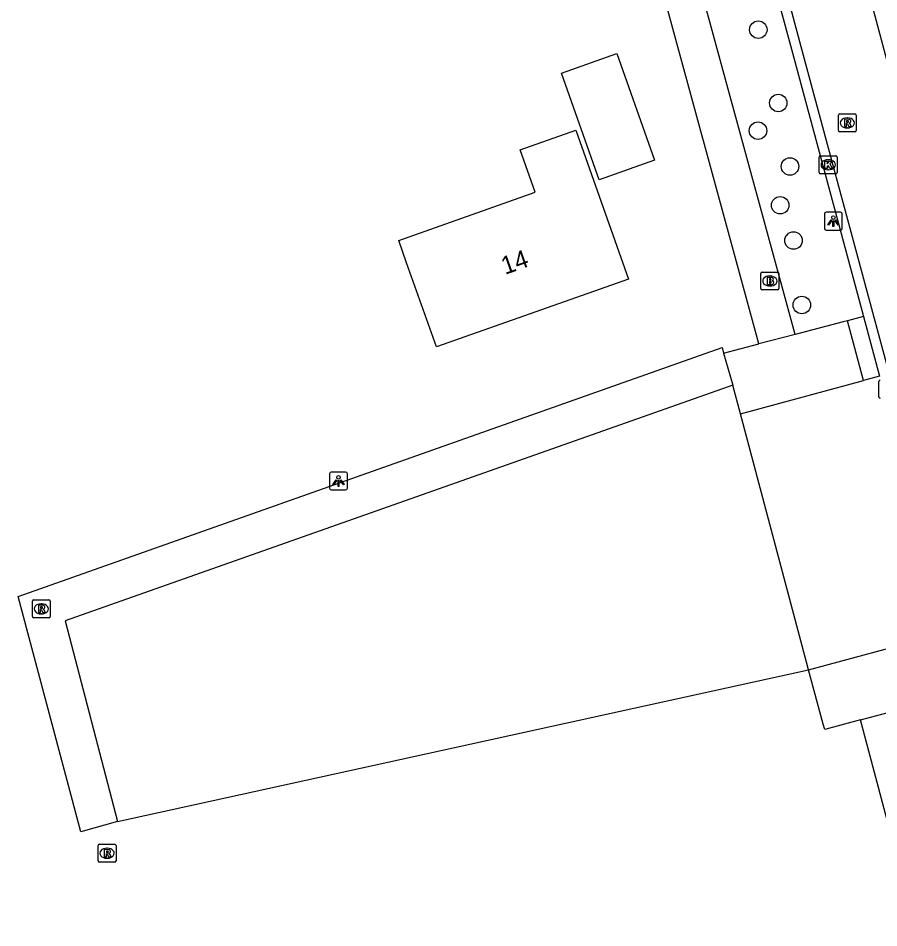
# Model space of a CAD drawing. Extents: x 162675 to 163482, y 379761 to 381227.
# Drawn here: x 162810 to 162858.2, y 380571.5 to 380622.3 of the extents above; entities that cross this region are included whole.
import ezdxf

# ---------------------------------------------------------------- set-up
doc = ezdxf.new("R2010")
doc.units = 0
for name, color, linetype in [('IMGEO_Boom', 7, 'Continuous'), ('IMGEO_Brandkraan', 7, 'Continuous'), ('IMGEO_Groenvoorziening', 7, 'Continuous'), ('IMGEO_Kolk', 7, 'Continuous'), ('IMGEO_Lichtpunt', 7, 'Continuous'), ('IMGEO_Pand', 7, 'Continuous'), ('IMGEO_Pand_nummerreeks', 7, 'Continuous'), ('IMGEO_Parkeervlak_open', 7, 'Continuous'), ('IMGEO_Rijbaan_lokaal_gesloten', 7, 'Continuous'), ('IMGEO_Rijbaan_lokaal_open', 7, 'Continuous'), ('IMGEO_Rioolput', 7, 'Continuous'), ('IMGEO_Voetpad_open', 7, 'Continuous')]:
    doc.layers.add(name, color=color, linetype=linetype)

msp = doc.modelspace()

# ---------------------------------------------------------------- linework, layer by layer
at = {"layer": 'IMGEO_Boom'}
for centre in [(162851.454, 380621.695), (162852.572, 380617.595), (162851.441, 380616.043), (162853.23, 380614.043), (162852.682, 380611.873), (162853.428, 380609.9), (162853.892, 380606.295)]:
    msp.add_circle(centre, 0.489, dxfattribs=at)
at = {"layer": 'IMGEO_Brandkraan'}
for p, q in [((162851.601, 380607.21), (162851.601, 380608.062)), ((162851.676, 380608.136), (162852.528, 380608.136)), ((162852.089, 380607.916), (162852.114, 380607.916)), ((162852.602, 380608.062), (162852.602, 380607.21)), ((162852.528, 380607.136), (162851.676, 380607.136)), ((162852.112, 380607.356), (162852.087, 380607.356))]:
    msp.add_line(p, q, dxfattribs=at)
for points in [[(162851.601, 380607.21), (162851.601, 380608.062)], [(162851.676, 380608.136), (162852.528, 380608.136)], [(162852.602, 380608.062), (162852.602, 380607.21)], [(162851.949, 380607.836), (162851.949, 380607.436), (162852.162, 380607.436)], [(162852.18, 380607.836), (162851.949, 380607.836)], [(162852.128, 380607.755), (162852.074, 380607.755), (162852.074, 380607.679)], [(162852.074, 380607.679), (162852.127, 380607.679)], [(162852.136, 380607.603), (162852.074, 380607.603), (162852.074, 380607.522)], [(162852.074, 380607.522), (162852.136, 380607.522)], [(162852.528, 380607.136), (162851.676, 380607.136)]]:
    msp.add_lwpolyline(points, dxfattribs=at)
for centre, radius, start, end in [((162851.678, 380608.06), 0.0765, 91.552, 178.448), ((162851.678, 380608.06), 0.0765, 91.552, 178.448), ((162852.526, 380608.06), 0.0765, 1.552, 88.448), ((162852.526, 380608.06), 0.0765, 1.552, 88.448), ((162852.129, 380607.717), 0.0379, 267.8285, 90.9355), ((162852.137, 380607.562), 0.0404, 269.8759, 90.5077), ((162852.168, 380607.687), 0.251, 268.6676, 293.5347), ((162852.184, 380607.691), 0.145, 59.4692, 91.5367), ((162852.209, 380607.738), 0.0922, 285.5137, 58.1501), ((162852.214, 380607.546), 0.105, 301.3115, 78.989), ((162851.678, 380607.212), 0.0765, 181.552, 268.448), ((162851.678, 380607.212), 0.0765, 181.552, 268.448), ((162852.526, 380607.212), 0.0765, 271.552, 358.448), ((162852.526, 380607.212), 0.0765, 271.552, 358.448)]:
    msp.add_arc(centre, radius, start, end, dxfattribs=at)
for centre, major_axis, ratio, start_param, end_param in [((162852.088, 380607.636), (-0.387, 0.002), 0.722429, 4.712389, 7.853982), ((162852.113, 380607.636), (-0.39, 0.002), 0.717154, 1.570796, 4.712389)]:
    msp.add_ellipse(centre, major_axis=major_axis, ratio=ratio, start_param=start_param, end_param=end_param, dxfattribs=at)
at = {"layer": 'IMGEO_Groenvoorziening'}
msp.add_lwpolyline([(162815.61, 380577.39), (162854.256, 380585.892)], dxfattribs=at)
at = {"layer": 'IMGEO_Kolk'}
for p, q in [((162854.864, 380613.712), (162854.864, 380614.564)), ((162854.939, 380614.638), (162855.791, 380614.638)), ((162855.865, 380614.564), (162855.865, 380613.712)), ((162855.352, 380614.418), (162855.377, 380614.418)), ((162855.791, 380613.638), (162854.939, 380613.638)), ((162855.375, 380613.858), (162855.35, 380613.858)), ((162858.198, 380601.153), (162858.198, 380602.005))]:
    msp.add_line(p, q, dxfattribs=at)
for points in [[(162854.864, 380613.712), (162854.864, 380614.564)], [(162854.939, 380614.638), (162855.791, 380614.638)], [(162855.865, 380614.564), (162855.865, 380613.712)], [(162855.185, 380614.338), (162855.308, 380614.338), (162855.308, 380614.187), (162855.438, 380614.338), (162855.602, 380614.338), (162855.456, 380614.187), (162855.609, 380613.938), (162855.457, 380613.938), (162855.372, 380614.102), (162855.308, 380614.035), (162855.308, 380613.938), (162855.185, 380613.938), (162855.185, 380614.338)], [(162855.791, 380613.638), (162854.939, 380613.638)], [(162858.198, 380601.153), (162858.198, 380602.005)]]:
    msp.add_lwpolyline(points, dxfattribs=at)
for centre, start, end in [((162854.941, 380614.562), 91.552, 178.448), ((162854.941, 380614.562), 91.552, 178.448), ((162855.789, 380614.562), 1.552, 88.448), ((162855.789, 380614.562), 1.552, 88.448), ((162854.941, 380613.714), 181.552, 268.448), ((162854.941, 380613.714), 181.552, 268.448), ((162855.789, 380613.714), 271.552, 358.448), ((162855.789, 380613.714), 271.552, 358.448), ((162858.275, 380602.003), 91.552, 178.448), ((162858.275, 380602.003), 91.552, 178.448), ((162858.275, 380601.155), 181.552, 268.448), ((162858.275, 380601.155), 181.552, 268.448)]:
    msp.add_arc(centre, 0.0765, start, end, dxfattribs=at)
for centre, major_axis, ratio, start_param, end_param in [((162855.351, 380614.138), (-0.387, 0.002), 0.722429, 4.712389, 7.853982), ((162855.376, 380614.138), (-0.39, 0.002), 0.717154, 1.570796, 4.712389)]:
    msp.add_ellipse(centre, major_axis=major_axis, ratio=ratio, start_param=start_param, end_param=end_param, dxfattribs=at)
at = {"layer": 'IMGEO_Lichtpunt'}
for p, q in [((162856.056, 380611.48), (162855.248, 380611.48)), ((162856.056, 380611.48), (162855.248, 380611.48)), ((162855.154, 380611.385), (162855.154, 380610.578)), ((162855.154, 380611.385), (162855.154, 380610.578)), ((162856.15, 380610.578), (162856.15, 380611.385)), ((162856.15, 380610.578), (162856.15, 380611.385)), ((162855.248, 380610.484), (162856.056, 380610.484)), ((162855.248, 380610.484), (162856.056, 380610.484)), ((162827.466, 380596.852), (162827.466, 380596.045)), ((162827.466, 380596.852), (162827.466, 380596.045)), ((162828.368, 380596.947), (162827.56, 380596.947)), ((162828.368, 380596.947), (162827.56, 380596.947)), ((162828.462, 380596.045), (162828.462, 380596.852)), ((162828.462, 380596.045), (162828.462, 380596.852)), ((162827.56, 380595.951), (162828.368, 380595.951)), ((162827.56, 380595.951), (162828.368, 380595.951))]:
    msp.add_line(p, q, dxfattribs=at)
for points in [[(162855.528, 380611.049), (162855.567, 380611.021), (162855.379, 380610.759), (162855.341, 380610.786), (162855.528, 380611.049)], [(162855.63, 380611.001), (162855.677, 380611.001), (162855.677, 380610.679), (162855.63, 380610.679), (162855.63, 380611.001)], [(162855.74, 380611.021), (162855.778, 380611.048), (162855.965, 380610.786), (162855.926, 380610.758), (162855.74, 380611.021)], [(162827.84, 380596.516), (162827.879, 380596.488), (162827.691, 380596.226), (162827.653, 380596.253), (162827.84, 380596.516)], [(162827.942, 380596.468), (162827.989, 380596.468), (162827.989, 380596.146), (162827.942, 380596.146), (162827.942, 380596.468)], [(162828.052, 380596.488), (162828.09, 380596.515), (162828.277, 380596.253), (162828.238, 380596.225), (162828.052, 380596.488)]]:
    msp.add_lwpolyline(points, dxfattribs=at)
for centre in [(162855.653, 380611.183), (162827.965, 380596.65)]:
    msp.add_circle(centre, 0.0994, dxfattribs=at)
for centre, start, end in [((162855.248, 380611.385), 90, 180), ((162855.248, 380611.385), 90, 180), ((162856.056, 380611.385), 0, 90), ((162856.056, 380611.385), 0, 90), ((162855.248, 380610.578), 180, 270), ((162855.248, 380610.578), 180, 270), ((162856.056, 380610.578), 270, 0), ((162856.056, 380610.578), 270, 360), ((162827.56, 380596.852), 90, 180), ((162827.56, 380596.852), 90, 180), ((162828.368, 380596.852), 0, 90), ((162828.368, 380596.852), 0, 90), ((162827.56, 380596.045), 180, 270), ((162827.56, 380596.045), 180, 270), ((162828.368, 380596.045), 270, 0), ((162828.368, 380596.045), 270, 360)]:
    msp.add_arc(centre, 0.0946, start, end, dxfattribs=at)
at = {"layer": 'IMGEO_Pand'}
for points in [[(162840.441, 380619.256), (162843.543, 380620.353), (162845.65, 380614.394), (162842.548, 380613.297), (162840.441, 380619.256)], [(162833.445, 380603.944), (162831.778, 380608.658), (162831.337, 380609.904), (162838.976, 380612.606), (162838.136, 380614.979), (162841.244, 380616.079), (162844.192, 380607.746), (162833.445, 380603.944)]]:
    msp.add_lwpolyline(points, dxfattribs=at)
at = {"layer": 'IMGEO_Parkeervlak_open'}
msp.add_lwpolyline([(162854.256, 380585.892), (162854.145, 380586.31), (162850.454, 380600.2)], dxfattribs=at)
at = {"layer": 'IMGEO_Rijbaan_lokaal_gesloten'}
for points in [[(162847.107, 380663.14), (162858.479, 380620.583), (162864.293, 380598.811), (162886.907, 380515.067), (162890.125, 380503.167)], [(162842.816, 380661.994), (162845.2, 380653.071), (162853.834, 380620.756), (162875.558, 380540.207)]]:
    msp.add_lwpolyline(points, dxfattribs=at)
at = {"layer": 'IMGEO_Rijbaan_lokaal_open'}
for points in [[(162845.436, 380650.19), (162846.559, 380645.717), (162849.741, 380633.782), (162853.306, 380620.608), (162857.003, 380606.907), (162857.345, 380605.64)], [(162857.345, 380605.64), (162858.243, 380602.314)]]:
    msp.add_lwpolyline(points, dxfattribs=at)
at = {"layer": 'IMGEO_Rioolput'}
for p, q in [((162855.935, 380616.054), (162855.935, 380616.906)), ((162856.01, 380616.98), (162856.862, 380616.98)), ((162856.423, 380616.76), (162856.448, 380616.76)), ((162856.936, 380616.906), (162856.936, 380616.054)), ((162856.446, 380616.2), (162856.421, 380616.2)), ((162856.862, 380615.98), (162856.01, 380615.98)), ((162810.839, 380588.868), (162810.839, 380589.72)), ((162810.914, 380589.794), (162811.766, 380589.794)), ((162811.327, 380589.574), (162811.352, 380589.574)), ((162811.84, 380589.72), (162811.84, 380588.868)), ((162811.766, 380588.794), (162810.914, 380588.794)), ((162811.35, 380589.014), (162811.325, 380589.014)), ((162814.517, 380575.197), (162814.517, 380576.049)), ((162814.592, 380576.123), (162815.444, 380576.123)), ((162815.005, 380575.903), (162815.03, 380575.903)), ((162815.518, 380576.049), (162815.518, 380575.197)), ((162815.028, 380575.343), (162815.003, 380575.343)), ((162815.444, 380575.123), (162814.592, 380575.123))]:
    msp.add_line(p, q, dxfattribs=at)
for points in [[(162855.935, 380616.054), (162855.935, 380616.906)], [(162856.01, 380616.98), (162856.862, 380616.98)], [(162856.524, 380616.678), (162856.272, 380616.68), (162856.272, 380616.28)], [(162856.45, 380616.599), (162856.396, 380616.599), (162856.396, 380616.518)], [(162856.936, 380616.906), (162856.936, 380616.054)], [(162856.272, 380616.28), (162856.396, 380616.28), (162856.396, 380616.442), (162856.407, 380616.442)], [(162856.396, 380616.518), (162856.448, 380616.518)], [(162856.454, 380616.413), (162856.525, 380616.28), (162856.665, 380616.28), (162856.6, 380616.406)], [(162856.862, 380615.98), (162856.01, 380615.98)], [(162810.839, 380588.868), (162810.839, 380589.72)], [(162810.914, 380589.794), (162811.766, 380589.794)], [(162811.84, 380589.72), (162811.84, 380588.868)], [(162811.428, 380589.492), (162811.176, 380589.494), (162811.176, 380589.094)], [(162811.176, 380589.094), (162811.3, 380589.094), (162811.3, 380589.256), (162811.311, 380589.256)], [(162811.354, 380589.413), (162811.3, 380589.413), (162811.3, 380589.332)], [(162811.3, 380589.332), (162811.352, 380589.332)], [(162811.358, 380589.227), (162811.429, 380589.094), (162811.569, 380589.094), (162811.504, 380589.22)], [(162811.766, 380588.794), (162810.914, 380588.794)], [(162814.517, 380575.197), (162814.517, 380576.049)], [(162814.592, 380576.123), (162815.444, 380576.123)], [(162815.518, 380576.049), (162815.518, 380575.197)], [(162815.106, 380575.821), (162814.854, 380575.823), (162814.854, 380575.423)], [(162814.854, 380575.423), (162814.978, 380575.423), (162814.978, 380575.585), (162814.989, 380575.585)], [(162815.032, 380575.742), (162814.978, 380575.742), (162814.978, 380575.661)], [(162814.978, 380575.661), (162815.03, 380575.661)], [(162815.036, 380575.556), (162815.107, 380575.423), (162815.247, 380575.423), (162815.182, 380575.549)], [(162815.444, 380575.123), (162814.592, 380575.123)]]:
    msp.add_lwpolyline(points, dxfattribs=at)
for centre, radius, start, end in [((162856.012, 380616.904), 0.0765, 91.552, 178.448), ((162856.012, 380616.904), 0.0765, 91.552, 178.448), ((162856.456, 380616.503), 0.0964, 77.0061, 93.1865), ((162856.47, 380616.56), 0.0378, 276.6634, 79.6772), ((162856.523, 380616.568), 0.109, 350.3612, 89.416), ((162856.521, 380616.568), 0.112, 277.5842, 350.9817), ((162856.86, 380616.904), 0.0765, 1.552, 88.448), ((162856.86, 380616.904), 0.0765, 1.552, 88.448), ((162856.012, 380616.056), 0.0765, 181.552, 268.448), ((162856.012, 380616.056), 0.0765, 181.552, 268.448), ((162856.406, 380616.389), 0.0533, 26.0293, 88.6989), ((162856.432, 380616.707), 0.19, 274.7715, 282.9687), ((162856.505, 380616.353), 0.108, 29.5134, 73.7905), ((162856.86, 380616.056), 0.0765, 271.552, 358.448), ((162856.86, 380616.056), 0.0765, 271.552, 358.448), ((162810.916, 380589.718), 0.0765, 91.552, 178.448), ((162810.916, 380589.718), 0.0765, 91.552, 178.448), ((162811.764, 380589.718), 0.0765, 1.552, 88.448), ((162811.764, 380589.718), 0.0765, 1.552, 88.448), ((162811.31, 380589.203), 0.0533, 26.0293, 88.6989), ((162811.336, 380589.521), 0.19, 274.7715, 282.9687), ((162811.36, 380589.317), 0.0964, 77.0061, 93.1865), ((162811.374, 380589.374), 0.0378, 276.6634, 79.6772), ((162811.427, 380589.382), 0.109, 350.3612, 89.416), ((162811.425, 380589.382), 0.112, 277.5842, 350.9817), ((162811.409, 380589.167), 0.108, 29.5134, 73.7905), ((162810.916, 380588.87), 0.0765, 181.552, 268.448), ((162810.916, 380588.87), 0.0765, 181.552, 268.448), ((162811.764, 380588.87), 0.0765, 271.552, 358.448), ((162811.764, 380588.87), 0.0765, 271.552, 358.448), ((162814.594, 380576.047), 0.0765, 91.552, 178.448), ((162814.594, 380576.047), 0.0765, 91.552, 178.448), ((162815.442, 380576.047), 0.0765, 1.552, 88.448), ((162815.442, 380576.047), 0.0765, 1.552, 88.448), ((162814.988, 380575.532), 0.0533, 26.0293, 88.6989), ((162815.014, 380575.85), 0.19, 274.7715, 282.9687), ((162815.038, 380575.646), 0.0964, 77.0061, 93.1865), ((162815.052, 380575.703), 0.0378, 276.6634, 79.6772), ((162815.105, 380575.711), 0.109, 350.3612, 89.416), ((162815.103, 380575.711), 0.112, 277.5842, 350.9817), ((162815.087, 380575.496), 0.108, 29.5134, 73.7905), ((162814.594, 380575.199), 0.0765, 181.552, 268.448), ((162814.594, 380575.199), 0.0765, 181.552, 268.448), ((162815.442, 380575.199), 0.0765, 271.552, 358.448), ((162815.442, 380575.199), 0.0765, 271.552, 358.448)]:
    msp.add_arc(centre, radius, start, end, dxfattribs=at)
for centre, major_axis, ratio, start_param, end_param in [((162856.422, 380616.48), (-0.387, 0.002), 0.722429, 4.712389, 7.853982), ((162856.447, 380616.48), (-0.39, 0.002), 0.717154, 1.570796, 4.712389), ((162811.326, 380589.294), (-0.387, 0.002), 0.722429, 4.712389, 7.853982), ((162811.351, 380589.294), (-0.39, 0.002), 0.717154, 1.570796, 4.712389), ((162815.004, 380575.623), (-0.387, 0.002), 0.722429, 4.712389, 7.853982), ((162815.029, 380575.623), (-0.39, 0.002), 0.717154, 1.570796, 4.712389)]:
    msp.add_ellipse(centre, major_axis=major_axis, ratio=ratio, start_param=start_param, end_param=end_param, dxfattribs=at)
at = {"layer": 'IMGEO_Voetpad_open'}
for points in [[(162853.512, 380604.643), (162853.343, 380605.263), (162841.385, 380649.111)], [(162851.481, 380604.114), (162851.349, 380604.6), (162839.36, 380648.572)], [(162856.446, 380605.406), (162856.211, 380605.345), (162853.512, 380604.643)], [(162857.345, 380605.64), (162856.446, 380605.406)], [(162857.351, 380602.071), (162856.446, 380605.406)], [(162853.512, 380604.643), (162851.481, 380604.114)], [(162815.61, 380577.39), (162813.557, 380576.827), (162810.045, 380589.989), (162849.428, 380603.921), (162849.517, 380603.603)], [(162849.517, 380603.603), (162851.481, 380604.114)], [(162849.517, 380603.603), (162850.024, 380601.801)], [(162858.243, 380602.314), (162857.351, 380602.071)], [(162850.024, 380601.801), (162812.665, 380588.632), (162815.61, 380577.39)], [(162850.454, 380600.2), (162850.024, 380601.801)], [(162850.454, 380600.2), (162857.351, 380602.071)], [(162854.256, 380585.892), (162861.186, 380587.749)], [(162857.178, 380583.078), (162855.172, 380582.539), (162855.09, 380582.837), (162854.256, 380585.892)], [(162857.178, 380583.078), (162859.28, 380583.642)], [(162869.049, 380538.459), (162868.949, 380538.835), (162857.178, 380583.078)]]:
    msp.add_lwpolyline(points, dxfattribs=at)

# ---------------------------------------------------------------- texts
at = {"layer": 'IMGEO_Pand_nummerreeks'}
msp.add_text('14', height=1, rotation=19.4824, dxfattribs=at).set_placement((162837.285, 380607.975))

doc.saveas('drawing.dxf')
